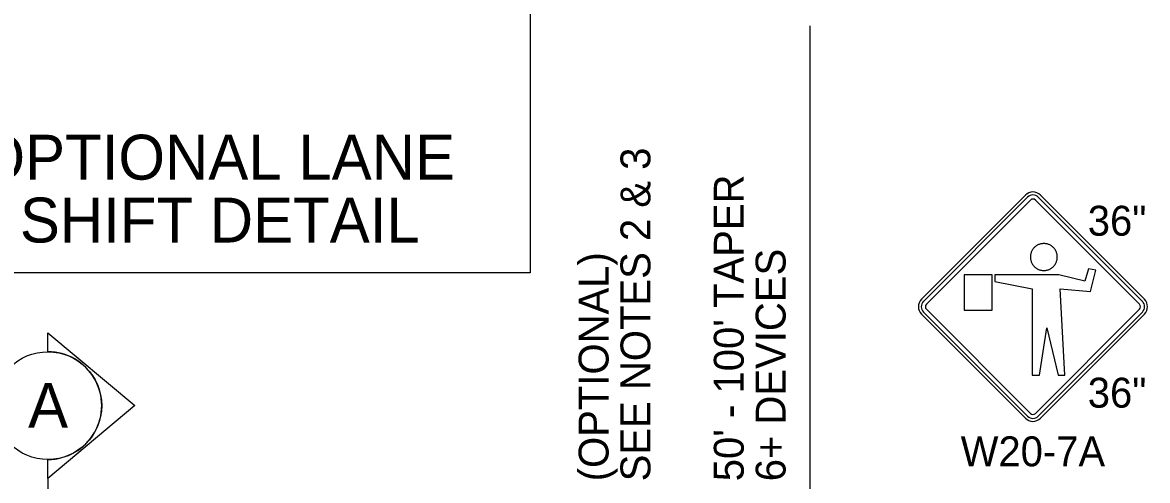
# Model space of a CAD drawing. Extents: x 99998.9 to 100095.7, y 99995 to 100010.7.
# Drawn here: x 100049.366 to 100052.376, y 100007.734 to 100008.958 of the extents above; entities that cross this region are included whole.
import ezdxf

# ---------------------------------------------------------------- set-up
doc = ezdxf.new("R2010")
doc.units = 0
for name, color, linetype in [('SH_DE_DetailHeading2Text', 7, 'Continuous'), ('SH_GI_SectionCut', 7, 'Continuous'), ('SH_TI_Tables', 7, 'Continuous'), ('TR_SN_ConstructionSigns', 7, 'Continuous'), ('TR_WZ_WorkZoneDetails', 7, 'Continuous'), ('TR_WZ_WorkZoneTextCurrent', 7, 'Continuous')]:
    doc.layers.add(name, color=color, linetype=linetype)

msp = doc.modelspace()

# ---------------------------------------------------------------- linework, layer by layer
at = {"layer": 'SH_GI_SectionCut'}
for p, q in [((100049.4337, 100008.0785), (100049.4337, 100008.1294)), ((100049.4337, 100008.1294), (100049.6664, 100007.9345)), ((100049.6664, 100007.9345), (100049.4337, 100007.7396)), ((100049.4337, 100007.7396), (100049.4337, 100007.7905)), ((100049.4338, 100007.7396), (100049.4338, 100005.4996))]:
    msp.add_line(p, q, dxfattribs=at)
msp.add_circle((100049.4338, 100007.9345), 0.144, dxfattribs=at)
msp.add_arc((100049.4338, 100007.9345), 0.144, 269.9978, 90.0022, dxfattribs=at)
at = {"layer": 'SH_TI_Tables'}
msp.add_lwpolyline([(100045.2702, 100010.325), (100050.7241, 100010.325), (100050.7241, 100008.2892), (100045.2702, 100008.2892)], close=True, dxfattribs=at)
at = {"layer": 'TR_SN_ConstructionSigns'}
for p, q in [((100052.0497, 100008.4972), (100051.7713, 100008.2188)), ((100052.0552, 100008.4917), (100051.7768, 100008.2132)), ((100051.7845, 100008.2055), (100052.063, 100008.4839)), ((100052.0762, 100008.4839), (100052.3546, 100008.2055)), ((100052.3624, 100008.2132), (100052.0839, 100008.4917)), ((100052.3679, 100008.2188), (100052.0895, 100008.4972)), ((100052.0813, 100008.3631), (100052.0797, 100008.3621)), ((100052.083, 100008.364), (100052.0813, 100008.3631)), ((100052.0847, 100008.3648), (100052.083, 100008.364)), ((100052.0865, 100008.3655), (100052.0847, 100008.3648)), ((100052.0884, 100008.3661), (100052.0865, 100008.3655)), ((100052.0902, 100008.3666), (100052.0884, 100008.3661)), ((100052.0921, 100008.367), (100052.0902, 100008.3666)), ((100052.094, 100008.3673), (100052.0921, 100008.367)), ((100052.0959, 100008.3675), (100052.094, 100008.3673)), ((100052.0978, 100008.3676), (100052.0959, 100008.3675)), ((100052.0997, 100008.3676), (100052.0978, 100008.3676)), ((100052.1016, 100008.3675), (100052.0997, 100008.3676)), ((100052.1036, 100008.3673), (100052.1016, 100008.3675)), ((100052.1054, 100008.367), (100052.1036, 100008.3673)), ((100052.1073, 100008.3666), (100052.1054, 100008.367)), ((100052.1091, 100008.3661), (100052.1073, 100008.3666)), ((100052.111, 100008.3655), (100052.1091, 100008.3661)), ((100052.1128, 100008.3648), (100052.111, 100008.3655)), ((100052.1145, 100008.364), (100052.1128, 100008.3648)), ((100052.1162, 100008.3631), (100052.1145, 100008.364)), ((100052.1179, 100008.3621), (100052.1162, 100008.3631)), ((100052.063, 100008.3354), (100052.0628, 100008.3335)), ((100052.0628, 100008.3335), (100052.0628, 100008.3316)), ((100052.0632, 100008.3373), (100052.063, 100008.3354)), ((100052.0636, 100008.3392), (100052.0632, 100008.3373)), ((100052.064, 100008.3411), (100052.0636, 100008.3392)), ((100052.0646, 100008.3429), (100052.064, 100008.3411)), ((100052.0652, 100008.3447), (100052.0646, 100008.3429)), ((100052.066, 100008.3465), (100052.0652, 100008.3447)), ((100052.0668, 100008.3482), (100052.066, 100008.3465)), ((100052.0677, 100008.3499), (100052.0668, 100008.3482)), ((100052.0688, 100008.3516), (100052.0677, 100008.3499)), ((100052.0698, 100008.3531), (100052.0688, 100008.3516)), ((100052.071, 100008.3546), (100052.0698, 100008.3531)), ((100052.0723, 100008.3561), (100052.071, 100008.3546)), ((100052.0737, 100008.3574), (100052.0723, 100008.3561)), ((100052.075, 100008.3587), (100052.0737, 100008.3574)), ((100052.0765, 100008.3599), (100052.075, 100008.3587)), ((100052.078, 100008.3611), (100052.0765, 100008.3599)), ((100052.0797, 100008.3621), (100052.078, 100008.3611)), ((100052.1195, 100008.3611), (100052.1179, 100008.3621)), ((100052.121, 100008.3599), (100052.1195, 100008.3611)), ((100052.1225, 100008.3587), (100052.121, 100008.3599)), ((100052.1239, 100008.3574), (100052.1225, 100008.3587)), ((100052.1252, 100008.3561), (100052.1239, 100008.3574)), ((100052.1265, 100008.3546), (100052.1252, 100008.3561)), ((100052.1276, 100008.3531), (100052.1265, 100008.3546)), ((100052.1288, 100008.3516), (100052.1276, 100008.3531)), ((100052.1298, 100008.3499), (100052.1288, 100008.3516)), ((100052.1307, 100008.3482), (100052.1298, 100008.3499)), ((100052.1315, 100008.3465), (100052.1307, 100008.3482)), ((100052.1323, 100008.3447), (100052.1315, 100008.3465)), ((100052.133, 100008.3429), (100052.1323, 100008.3447)), ((100052.1335, 100008.3411), (100052.133, 100008.3429)), ((100052.134, 100008.3392), (100052.1335, 100008.3411)), ((100052.1343, 100008.3373), (100052.134, 100008.3392)), ((100052.1346, 100008.3354), (100052.1343, 100008.3373)), ((100052.1347, 100008.3335), (100052.1346, 100008.3354)), ((100052.1348, 100008.3316), (100052.1347, 100008.3335)), ((100052.0628, 100008.3316), (100052.0628, 100008.3297)), ((100052.0628, 100008.3297), (100052.063, 100008.3278)), ((100052.063, 100008.3278), (100052.0632, 100008.3259)), ((100052.0632, 100008.3259), (100052.0636, 100008.324)), ((100052.0636, 100008.324), (100052.064, 100008.3221)), ((100052.064, 100008.3221), (100052.0646, 100008.3203)), ((100052.0646, 100008.3203), (100052.0652, 100008.3185)), ((100052.0652, 100008.3185), (100052.066, 100008.3167)), ((100052.066, 100008.3167), (100052.0668, 100008.315)), ((100052.0668, 100008.315), (100052.0677, 100008.3133)), ((100052.0677, 100008.3133), (100052.0688, 100008.3117)), ((100052.0688, 100008.3117), (100052.0698, 100008.3101)), ((100052.0698, 100008.3101), (100052.071, 100008.3086)), ((100052.071, 100008.3086), (100052.0723, 100008.3072)), ((100052.0723, 100008.3072), (100052.0737, 100008.3058)), ((100052.0737, 100008.3058), (100052.075, 100008.3045)), ((100052.075, 100008.3045), (100052.0765, 100008.3033)), ((100052.0765, 100008.3033), (100052.078, 100008.3021)), ((100052.1195, 100008.3021), (100052.121, 100008.3033)), ((100052.121, 100008.3033), (100052.1225, 100008.3045)), ((100052.1225, 100008.3045), (100052.1239, 100008.3058)), ((100052.1239, 100008.3058), (100052.1252, 100008.3072)), ((100052.1252, 100008.3072), (100052.1265, 100008.3086)), ((100052.1265, 100008.3086), (100052.1276, 100008.3101)), ((100052.1276, 100008.3101), (100052.1288, 100008.3117)), ((100052.1288, 100008.3117), (100052.1298, 100008.3133)), ((100052.1298, 100008.3133), (100052.1307, 100008.315)), ((100052.1307, 100008.315), (100052.1315, 100008.3167)), ((100052.1315, 100008.3167), (100052.1323, 100008.3185)), ((100052.1323, 100008.3185), (100052.133, 100008.3203)), ((100052.133, 100008.3203), (100052.1335, 100008.3221)), ((100052.1335, 100008.3221), (100052.134, 100008.324)), ((100052.134, 100008.324), (100052.1343, 100008.3259)), ((100052.1343, 100008.3259), (100052.1346, 100008.3278)), ((100052.1346, 100008.3278), (100052.1347, 100008.3297)), ((100052.1347, 100008.3297), (100052.1348, 100008.3316)), ((100051.8853, 100008.2843), (100051.8853, 100008.1896)), ((100051.9607, 100008.2843), (100051.8853, 100008.2843)), ((100051.9607, 100008.1896), (100051.9607, 100008.2843)), ((100052.139, 100008.2843), (100051.9677, 100008.2843)), ((100051.9677, 100008.2843), (100051.9677, 100008.2662)), ((100052.078, 100008.3021), (100052.0797, 100008.3011)), ((100052.0797, 100008.3011), (100052.0813, 100008.3001)), ((100052.0813, 100008.3001), (100052.083, 100008.2992)), ((100052.083, 100008.2992), (100052.0847, 100008.2984)), ((100052.0847, 100008.2984), (100052.0865, 100008.2977)), ((100052.0865, 100008.2977), (100052.0884, 100008.2971)), ((100052.0884, 100008.2971), (100052.0902, 100008.2966)), ((100052.0902, 100008.2966), (100052.0921, 100008.2962)), ((100052.0921, 100008.2962), (100052.094, 100008.2959)), ((100052.094, 100008.2959), (100052.0959, 100008.2957)), ((100052.0959, 100008.2957), (100052.0978, 100008.2956)), ((100052.0978, 100008.2956), (100052.0997, 100008.2956)), ((100052.0997, 100008.2956), (100052.1016, 100008.2957)), ((100052.1016, 100008.2957), (100052.1036, 100008.2959)), ((100052.1036, 100008.2959), (100052.1054, 100008.2962)), ((100052.1054, 100008.2962), (100052.1073, 100008.2966)), ((100052.1073, 100008.2966), (100052.1091, 100008.2971)), ((100052.1091, 100008.2971), (100052.111, 100008.2977)), ((100052.111, 100008.2977), (100052.1128, 100008.2984)), ((100052.1128, 100008.2984), (100052.1145, 100008.2992)), ((100052.1145, 100008.2992), (100052.1162, 100008.3001)), ((100052.1162, 100008.3001), (100052.1179, 100008.3011)), ((100052.1179, 100008.3011), (100052.1195, 100008.3021)), ((100052.2086, 100008.2671), (100052.139, 100008.2843)), ((100052.2183, 100008.3), (100052.2086, 100008.2671)), ((100052.2382, 100008.2964), (100052.2183, 100008.3)), ((100052.2232, 100008.2396), (100052.2382, 100008.2964)), ((100051.9677, 100008.2662), (100052.0672, 100008.2464)), ((100052.0672, 100008.2464), (100052.0672, 100008.0161)), ((100052.1553, 100008.0161), (100052.1422, 100008.2465)), ((100052.1422, 100008.2465), (100052.2232, 100008.2396)), ((100051.7768, 100008.1845), (100052.0552, 100007.9061)), ((100052.063, 100007.9138), (100051.7845, 100008.1923)), ((100051.8853, 100008.1896), (100051.9607, 100008.1896)), ((100052.3546, 100008.1923), (100052.0762, 100007.9138)), ((100052.0839, 100007.9061), (100052.3624, 100008.1845)), ((100051.7713, 100008.179), (100052.0497, 100007.9006)), ((100052.0895, 100007.9006), (100052.3679, 100008.179)), ((100052.0874, 100008.0161), (100052.107, 100008.1428)), ((100052.107, 100008.1428), (100052.1373, 100008.0161)), ((100052.0672, 100008.0161), (100052.0874, 100008.0161)), ((100052.1373, 100008.0161), (100052.1553, 100008.0161))]:
    msp.add_line(p, q, dxfattribs=at)
for centre, radius, start, end in [((100052.0696, 100008.4773), 0.0281, 45, 135), ((100052.0696, 100008.4773), 0.0203, 45, 135), ((100052.0696, 100008.4773), 0.00937, 45, 135), ((100051.7912, 100008.1989), 0.0281, 135, 225), ((100051.7912, 100008.1989), 0.0203, 135, 225), ((100052.348, 100008.1989), 0.0203, 315, 45), ((100052.348, 100008.1989), 0.0281, 315, 45), ((100051.7912, 100008.1989), 0.00937, 135, 225), ((100052.348, 100008.1989), 0.00937, 315, 45), ((100052.0696, 100007.9205), 0.00937, 225, 315), ((100052.0696, 100007.9205), 0.0281, 225, 315), ((100052.0696, 100007.9205), 0.0203, 225, 315)]:
    msp.add_arc(centre, radius, start, end, dxfattribs=at)
at = {"layer": 'TR_WZ_WorkZoneDetails'}
msp.add_line((100051.4733, 100007.0923), (100051.4733, 100008.9491), dxfattribs=at)

# ---------------------------------------------------------------- texts
at = {"layer": 'SH_DE_DetailHeading2Text'}
for s, p in [('OPTIONAL LANE', (100049.248, 100008.5384)), ('SHIFT DETAIL', (100049.3589, 100008.3704))]:
    msp.add_text(s, height=0.12, rotation=360, dxfattribs=at).set_placement(p)
at = {"layer": 'SH_GI_SectionCut'}
msp.add_text('A', height=0.12, rotation=359.99, dxfattribs=at).set_placement((100049.3809, 100007.8754))
at = {"layer": 'TR_SN_ConstructionSigns'}
for s, p in [('36"', (100052.2163, 100008.3887)), ('36"', (100052.2163, 100007.9291)), ('W20-7A', (100051.8763, 100007.7723))]:
    msp.add_text(s, height=0.08, rotation=360, dxfattribs=at).set_placement(p)
at = {"layer": 'TR_WZ_WorkZoneTextCurrent'}
for s, p in [('SEE NOTES 2 & 3', (100051.046, 100007.7323)), ("50' - 100' TAPER", (100051.2957, 100007.7323)), ('(OPTIONAL)', (100050.934, 100007.7323)), ('6+ DEVICES', (100051.4077, 100007.7323))]:
    msp.add_text(s, height=0.08, rotation=90, dxfattribs=at).set_placement(p)

doc.saveas('drawing.dxf')
